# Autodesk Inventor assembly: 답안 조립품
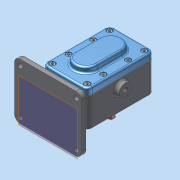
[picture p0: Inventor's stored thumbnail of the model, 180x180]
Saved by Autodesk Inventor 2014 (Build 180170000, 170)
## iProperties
Created: 2026-10
Part Number: 답안 조립품
Document SubType Name: Assembly
Designer: dg
Author: dg
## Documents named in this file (11)
- C:\Users\dg\Desktop\761003V1011\답안 조립품.iam
- C:\Users\dg\Desktop\761003V1011\본체.ipt
- C:\Users\dg\Desktop\761003V1011\가져온 구성요소\6각 구멍붙이 볼트 M5x16\6각 구멍붙이 볼트 M5x16.ipt
- C:\Users\dg\Desktop\761003V1011\가져온 구성요소\개스킷\개스킷.ipt
- C:\Users\dg\Desktop\761003V1011\가져온 구성요소\구동 축\구동 축.ipt
- C:\Users\dg\Desktop\761003V1011\가져온 구성요소\베어링 부시\베어링 부시.ipt
- C:\Users\dg\Desktop\761003V1011\가져온 구성요소\스퍼 기어\스퍼 기어.ipt
- C:\Users\dg\Desktop\761003V1011\가져온 구성요소\오일 실 16 28 7\오일 실 16 28 7.ipt
- C:\Users\dg\Desktop\761003V1011\가져온 구성요소\종동 축\종동 축.ipt
- C:\Users\dg\Desktop\761003V1011\가져온 구성요소\커버\커버.ipt
- C:\Users\dg\Desktop\761003V1011\가져온 구성요소\평행 키 6x6x18\평행 키 6x6x18.ipt
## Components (10 placed, 3 different names)
1. 6각 구멍붙이 볼트 M5x16:1
2. 개스킷:1
3. 구동 축:1
4. 6각 구멍붙이 볼트 M5x16:2
5. 6각 구멍붙이 볼트 M5x16:3
6. 6각 구멍붙이 볼트 M5x16:4
7. 6각 구멍붙이 볼트 M5x16:5
8. 6각 구멍붙이 볼트 M5x16:6
9. 6각 구멍붙이 볼트 M5x16:7
10. 6각 구멍붙이 볼트 M5x16:8
